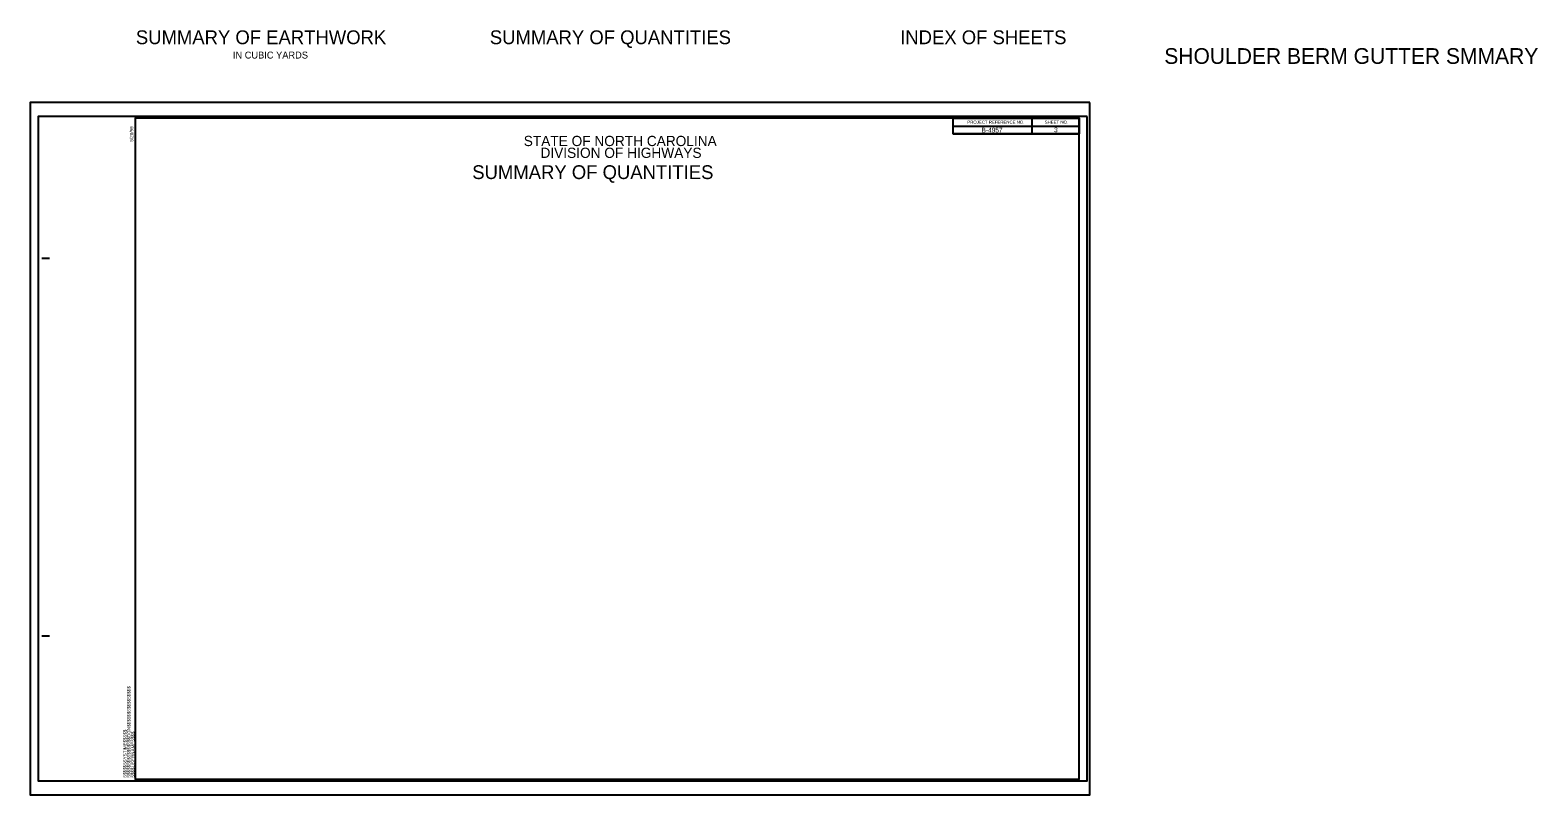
# Model space of a CAD drawing. Extents: x 2109603 to 2111999, y 434786 to 437408.
# Drawn here: x 2109603 to 2111999, y 434786 to 436001 of the extents above; entities that cross this region are included whole.
import ezdxf

# ---------------------------------------------------------------- set-up
doc = ezdxf.new("R2010")
doc.units = 0
for name, color, linetype in [('Sheet Cutting Line CELL', 7, 'Continuous'), ('Sheet Data Field CELL', 7, 'Continuous'), ('Sheet Plot Border Inside CELL', 7, 'Continuous'), ('Sheet Plot Border Outside CELL', 7, 'Continuous'), ('Sheet Summary CELL', 7, 'Continuous'), ('Sheet Summary Earthwork CELL', 7, 'Continuous')]:
    doc.layers.add(name, color=color, linetype=linetype)

msp = doc.modelspace()

# ---------------------------------------------------------------- linework, layer by layer
at = {"layer": 'Sheet Cutting Line CELL'}
for p, q in [((2111286.6, 435886.3), (2109602.6, 435886.3)), ((2109602.6, 435886.3), (2109602.6, 434786.3)), ((2109602.6, 434786.3), (2111286.6, 434786.3))]:
    msp.add_line(p, q, dxfattribs=at)
at = {"layer": 'Sheet Plot Border Inside CELL'}
msp.add_lwpolyline([(2111282.1, 435863.9), (2109615.6, 435863.9), (2109615.6, 434808.8), (2111282.1, 434808.8)], close=True, dxfattribs=at)
at = {"layer": 'Sheet Plot Border Outside CELL'}
msp.add_lwpolyline([(2111286.6, 435886.3), (2109602.6, 435886.3), (2109602.6, 434786.3), (2111286.6, 434786.3)], close=True, dxfattribs=at)
at = {"layer": 'Sheet Summary CELL'}
for p, q in [((2109769.6, 435861.3), (2109769.6, 435820.9)), ((2111069.6, 435848.8), (2111269.6, 435848.8)), ((2111194.6, 435861.3), (2111194.6, 435836.3)), ((2111069.6, 435836.3), (2111269.6, 435836.3)), ((2110519.2, 435772.5), (2110519.2, 435772.5)), ((2109621.1, 435638.8), (2109633.6, 435638.8)), ((2109621.1, 435038.8), (2109633.6, 435038.8)), ((2109769.6, 434811.3), (2109769.6, 434811.3)), ((2109769.6, 434811.3), (2109769.6, 434811.3)), ((2109769.6, 434811.3), (2109769.6, 434811.3)), ((2109769.6, 434811.3), (2109769.6, 434811.3)), ((2109769.6, 434811.3), (2109769.6, 434811.3)), ((2109769.6, 434811.3), (2109769.6, 434811.3))]:
    msp.add_line(p, q, dxfattribs=at)
for points in [[(2111269.6, 435861.3), (2109769.6, 435861.3), (2109769.6, 434811.3), (2111269.6, 434811.3)], [(2111069.6, 435861.3), (2111269.6, 435861.3), (2111269.6, 435836.3), (2111069.6, 435836.3)]]:
    msp.add_lwpolyline(points, close=True, dxfattribs=at)
msp.add_lwpolyline([(2109907.1, 434811.3), (2109907.1, 434811.3)], dxfattribs=at)

# ---------------------------------------------------------------- texts
at = {"layer": 'Sheet Data Field CELL'}
for s, p in [('B-4957', (2111114.5, 435838.8)), ('3', (2111229.8, 435839.1))]:
    msp.add_text(s, height=7.5, dxfattribs=at).set_placement(p)
at = {"layer": 'Sheet Summary CELL'}
for s, height, p in [('SUMMARY OF EARTHWORK', 21.95, (2109770.6, 435979)), ('SUMMARY OF QUANTITIES', 21.95, (2110333.1, 435979)), ('INDEX OF SHEETS', 21.95, (2110985.2, 435979)), ('IN CUBIC YARDS', 11, (2109924.8, 435956.2)), ('PROJECT REFERENCE NO.', 5, (2111091.8, 435852.6)), ('SHEET NO.', 5, (2111214.9, 435852.5)), ('STATE OF NORTH CAROLINA', 16.25, (2110387, 435817.1)), ('DIVISION OF HIGHWAYS', 16.25, (2110413.6, 435798.3)), ('SUMMARY OF QUANTITIES', 21.95, (2110305.2, 435764.7))]:
    msp.add_text(s, height=height, dxfattribs=at).set_placement(p)
for s, p in [('5/28/99', (2109766.4, 435824.2)), ('$$$$$$$$$$$$$$$$DGN$$$$$$$$$$$$$$$$', (2109762, 434813.7)), ('$$$$$$SYSTIME$$$$$', (2109755.9, 434813.7)), ('$$$$USERNAME$$$$', (2109768.5, 434813.7))]:
    msp.add_text(s, height=5.25, rotation=90, dxfattribs=at).set_placement(p)
at = {"layer": 'Sheet Summary Earthwork CELL'}
msp.add_text('SHOULDER BERM GUTTER SMMARY', height=25, dxfattribs=at).set_placement((2111404.9, 435947.7))

doc.saveas('drawing.dxf')
